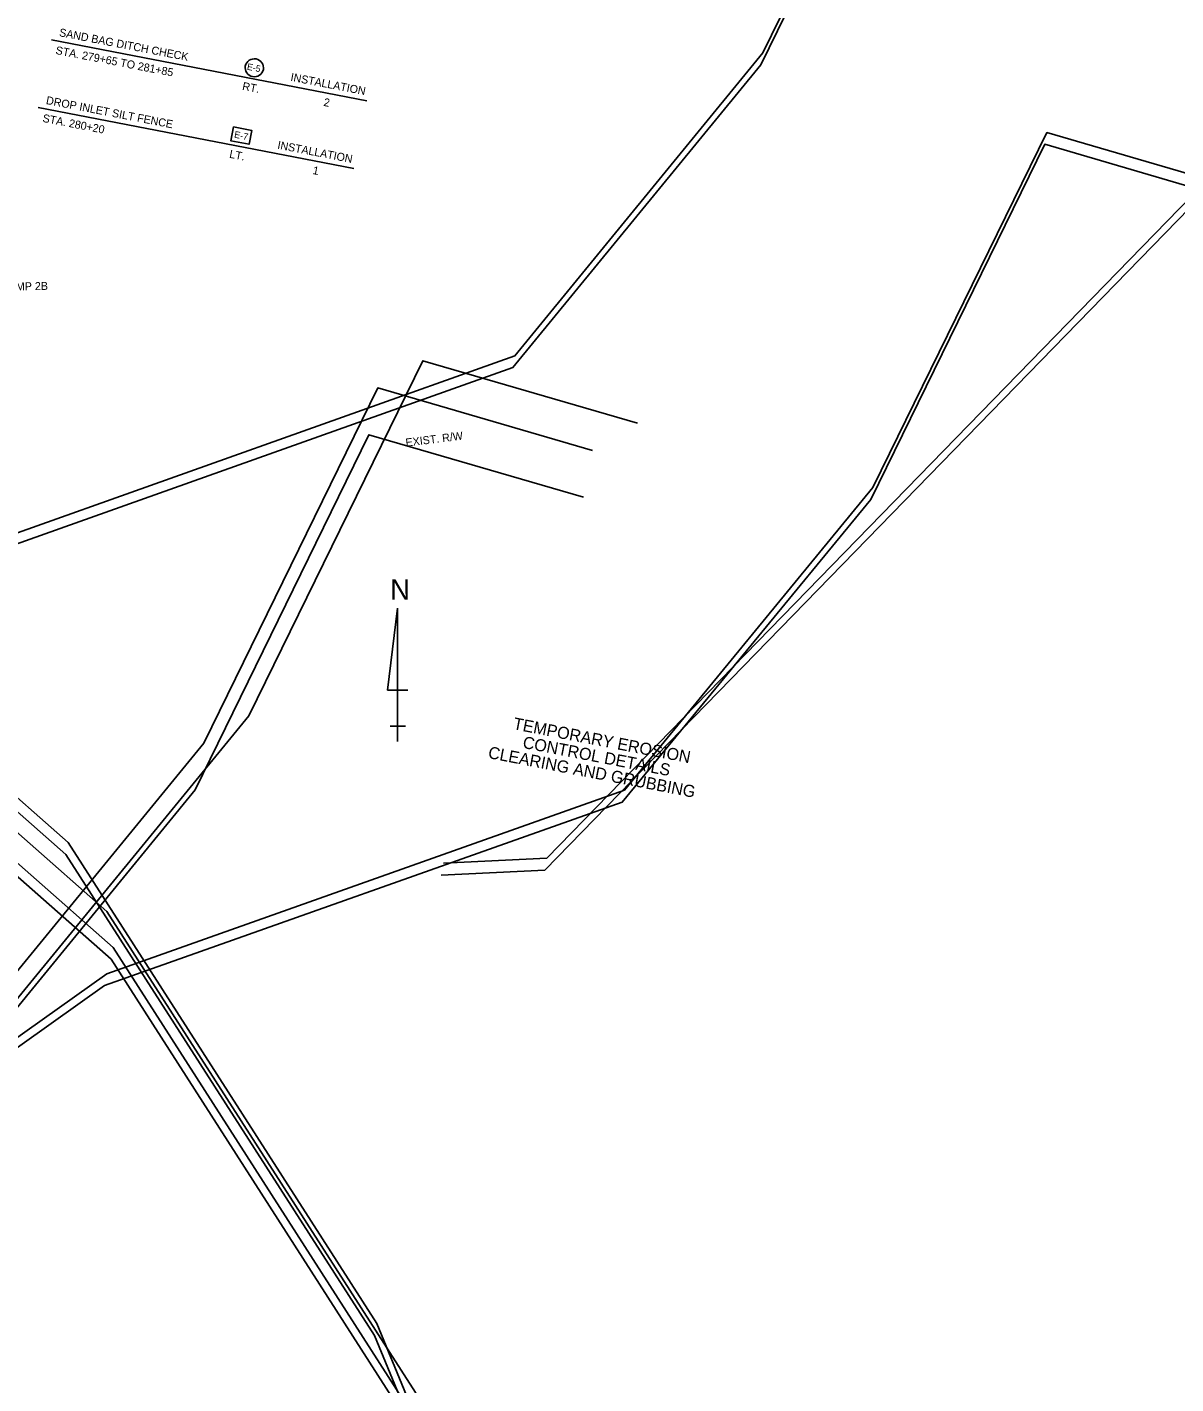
# Model space of a CAD drawing. Extents: x 605579 to 613541, y 415511 to 420599.
# Drawn here: x 611043 to 611905, y 418408 to 419425 of the extents above; entities that cross this region are included whole.
import ezdxf

# ---------------------------------------------------------------- set-up
doc = ezdxf.new("R2010")
doc.units = 0
for name, color, linetype in [('Default', 7, 'Continuous'), ('R_Bench', 7, 'Continuous'), ('R_Draft', 7, 'Continuous'), ('R_Island', 7, 'Continuous'), ('R_Slope Break', 7, 'Continuous'), ('R_Subgrade', 7, 'Continuous'), ('X_Phi Angle_SB', 7, 'Continuous')]:
    doc.layers.add(name, color=color, linetype=linetype)

msp = doc.modelspace()

# ---------------------------------------------------------------- linework, layer by layer
at = {"layer": 'R_Bench'}
for p, q in [((611061.4, 419415.9), (611298, 419370.2)), ((611051.5, 419365.1), (611288.2, 419319.4))]:
    msp.add_line(p, q, dxfattribs=at)
at = {"layer": 'R_Draft'}
for p, q in [((611431.5, 418793.3), (611353.8, 418789.6)), ((611433.1, 418802.2), (611355.4, 418798.4))]:
    msp.add_line(p, q, dxfattribs=at)
for points in [[(612675.2, 419968), (612326.2, 419719.3), (611433.1, 418802.2)], [(612673.6, 419959.2), (612324.6, 419710.4), (611431.5, 418793.3)], [(611886.5, 419625.7), (611725.4, 419672.4), (611595.1, 419406.1)], [(611884.9, 419616.8), (611723.9, 419663.6), (611593.5, 419397.2)], [(611595.1, 419406.1), (611409.1, 419179), (611020.9, 419041)], [(611593.5, 419397.2), (611407.5, 419170.1), (611019.3, 419032.1)], [(610676.8, 419366.3), (610765, 419086.3), (611074, 418813.9)], [(610675, 419357.5), (610763.3, 419077.5), (611072.3, 418805.1)], [(611969.1, 419299.4), (611808.1, 419346.3), (611677.5, 419080.1)], [(611967.5, 419290.5), (611806.5, 419337.5), (611675.9, 419071.2)], [(610705.8, 419314.7), (610794, 419034.7), (611103, 418762.2)], [(610710.5, 419287.7), (610798.7, 419007.8), (611107.8, 418735.3)], [(610708.8, 419278.9), (610797, 418998.9), (611106.1, 418726.5)], [(611500.9, 419128.4), (611339.9, 419175.2), (611209.5, 418908.9)], [(611467.2, 419108), (611306.2, 419154.8), (611175.8, 418888.4)], [(611460.6, 419072.9), (611299.6, 419119.7), (611169.2, 418853.4)], [(611677.5, 419080.1), (611491.2, 418853.2), (611102.9, 418715.6)], [(611675.9, 419071.2), (611489.6, 418844.3), (611101.3, 418706.8)], [(611209.5, 418908.9), (611023.5, 418681.8), (610635.3, 418543.9)], [(611175.8, 418888.4), (610989.8, 418661.4), (610601.6, 418523.4)], [(611169.2, 418853.4), (610983.2, 418626.3), (610595, 418488.4)], [(611074, 418813.9), (611305.4, 418453.2), (611793.4, 417269.7)], [(611072.3, 418805.1), (611303.7, 418444.3), (611791.7, 417260.9)], [(611103, 418762.2), (611334.4, 418401.5), (611822.4, 417218.1)], [(611107.8, 418735.3), (611339.1, 418374.6), (611827.1, 417191.2)], [(611106.1, 418726.5), (611337.4, 418365.8), (611825.4, 417182.3)], [(611102.9, 418715.6), (610753.7, 418467.3), (609859.5, 417551.2)], [(611101.3, 418706.8), (610752.1, 418458.4), (609857.9, 417542.3)]]:
    msp.add_lwpolyline(points, dxfattribs=at)
at = {"layer": 'R_Slope Break'}
msp.add_lwpolyline([(611197.9, 419350.5), (611211.7, 419347.9), (611209.7, 419337.6), (611195.9, 419340.2)], close=True, dxfattribs=at)
msp.add_ellipse((611213.6, 419394.9), major_axis=(-6.76, 1.31), ratio=0.97521, dxfattribs=at)
at = {"layer": 'X_Phi Angle_SB'}
for p, q in [((611321.1, 418989.6), (611313.4, 418928.1)), ((611321.1, 418889.6), (611321.1, 418989.6)), ((611321.1, 418989.6), (611321.1, 418912.7)), ((611313.4, 418928.1), (611328.8, 418928.1)), ((611321.1, 418889.6), (611321.1, 418912.7)), ((611321.1, 418901.2), (611315.4, 418901.2)), ((611315.4, 418901.2), (611326.9, 418901.2)), ((611321.1, 418889.6), (611321.1, 418901.2))]:
    msp.add_line(p, q, dxfattribs=at)

# ---------------------------------------------------------------- texts
at = {"layer": 'Default'}
msp.add_text('C.L. RAMP 2B', height=6, rotation=1.1692, dxfattribs=at).set_placement((611006.7, 419227.3))
at = {"layer": 'R_Bench'}
for s, p in [('SAND BAG DITCH CHECK', (611066.8, 419418.7)), ('STA. 279+65 TO 281+85', (611064.2, 419405.3)), ('RT.', (611204.2, 419378.4)), ('INSTALLATION', (611240.4, 419385.2)), ('DROP INLET SILT FENCE', (611057, 419367.8)), ('2', (611265.2, 419366.4)), ('STA. 280+20', (611054.4, 419354.4)), ('LT.', (611194.5, 419327.5)), ('INSTALLATION', (611230.6, 419334.3)), ('1', (611257, 419315.3))]:
    msp.add_text(s, height=6, rotation=349.0745, dxfattribs=at).set_placement(p)
at = {"layer": 'R_Island'}
for s, p in [('TEMPORARY EROSION ', (611407.2, 418899)), (' CLEARING AND GRUBBING', (611385.2, 418878)), ('CONTROL DETAILS', (611414.4, 418885))]:
    msp.add_text(s, height=9, rotation=349.0745, dxfattribs=at).set_placement(p)
at = {"layer": 'R_Slope Break'}
for s, height, rotation, p in [('E-5', 4.88, 349.0745, (611207.8, 419393.5)), ('E-7', 5, 348.6922, (611198.2, 419342.6))]:
    msp.add_text(s, height=height, rotation=rotation, dxfattribs=at).set_placement(p)
at = {"layer": 'R_Subgrade'}
msp.add_text('EXIST. R/W', height=6, rotation=7.1103, dxfattribs=at).set_placement((611327.4, 419110.8))
at = {"layer": 'X_Phi Angle_SB'}
msp.add_text('N', height=15.4, rotation=360, dxfattribs=at).set_placement((611315.5, 418996))

doc.saveas('drawing.dxf')
